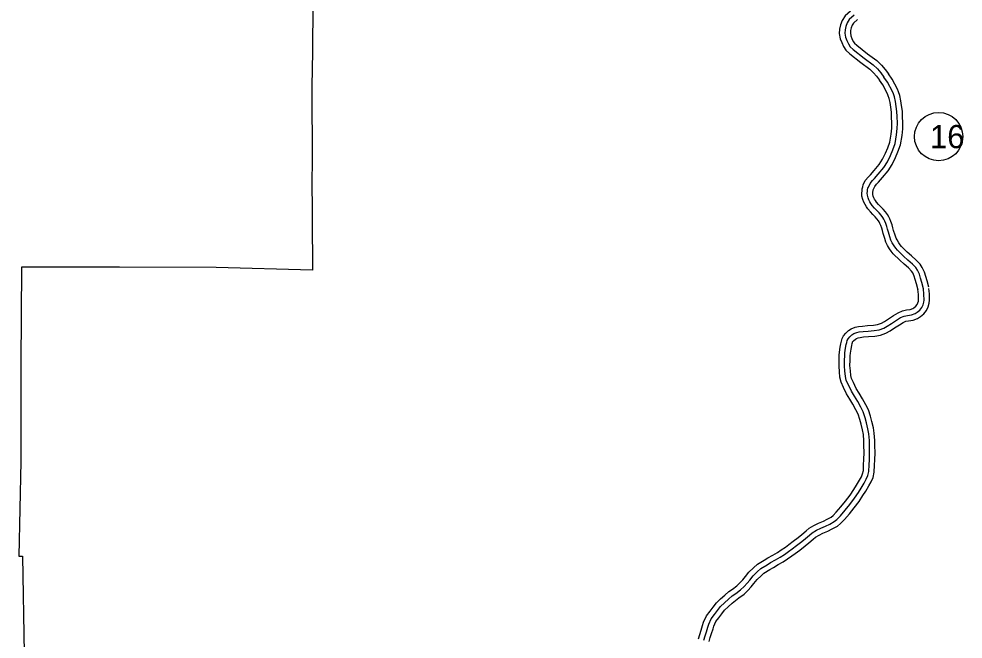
# Model space of a CAD drawing. Extents: x -83719 to 153526, y -11835 to 11446.
# Drawn here: x -2435 to -1575, y 2786 to 3351 of the extents above; entities that cross this region are included whole.
import ezdxf

# ---------------------------------------------------------------- set-up
doc = ezdxf.new("R2010")
doc.units = 0
for name, color, linetype in [('Level 10', 7, 'Continuous'), ('Level 2', 7, 'Continuous'), ('Level 27', 7, 'Continuous'), ('Level 59', 7, 'Continuous')]:
    doc.layers.add(name, color=color, linetype=linetype)

msp = doc.modelspace()

# ---------------------------------------------------------------- linework, layer by layer
at = {"layer": 'Level 10'}
for points in [[(-1677.93, 3358.27), (-1682.78, 3353.99), (-1685.38, 3349.91), (-1686.84, 3345.86), (-1687.68, 3342.04), (-1688.03, 3337.83), (-1687.11, 3333.21), (-1685.81, 3329.63), (-1684.16, 3326.02), (-1682, 3322.61), (-1678.52, 3319.56), (-1668.41, 3311.43), (-1660.31, 3305.5), (-1656.75, 3302.17), (-1654.01, 3299.1), (-1651.52, 3295.47)], [(-1671.31, 3350.79), (-1675.1, 3347.43), (-1676.35, 3345.46), (-1677.21, 3343.08), (-1677.77, 3340.55), (-1677.95, 3338.4), (-1677.45, 3335.9), (-1676.56, 3333.43), (-1675.35, 3330.8), (-1674.32, 3329.18), (-1672.09, 3327.22), (-1662.32, 3319.37), (-1653.91, 3313.21), (-1649.59, 3309.16), (-1646.13, 3305.28), (-1643.27, 3301.12)], [(-1606.59, 3106.74), (-1608.16, 3112.5), (-1609.2, 3116.53), (-1610.49, 3120.56), (-1612.51, 3124.87), (-1614.54, 3127.82), (-1617.95, 3131.53), (-1622.22, 3135.32), (-1626.24, 3138.86), (-1631.43, 3143.93), (-1632.51, 3145.31), (-1633.83, 3147.36), (-1635.48, 3149.85), (-1636.32, 3151.52), (-1637.15, 3154.24), (-1638.56, 3158.46), (-1639.16, 3160.87), (-1639.89, 3163.63), (-1641.05, 3166.8), (-1641.99, 3168.99), (-1642.97, 3171.07), (-1644.21, 3173.1), (-1646.1, 3175.53), (-1648.12, 3177.81), (-1650.18, 3180), (-1652.23, 3182.23), (-1654.07, 3184.35), (-1655.11, 3185.78), (-1655.9, 3187.01), (-1656.54, 3188.29), (-1657.06, 3189.63), (-1657.48, 3191.35), (-1657.54, 3192.32), (-1657.41, 3193.53), (-1657.27, 3194.88), (-1657.12, 3195.47), (-1656.86, 3196.2), (-1655.76, 3198.62), (-1654.09, 3200.7), (-1652.33, 3202.47), (-1648.7, 3206.71), (-1643.58, 3212.79), (-1639.81, 3218.73), (-1636.92, 3224.89), (-1634.65, 3230.1), (-1632.45, 3236.49), (-1630.84, 3244.92), (-1630.28, 3251.22), (-1630.17, 3256.44), (-1630.39, 3262.45), (-1630.63, 3267.26), (-1631.35, 3272.29), (-1632, 3276.74), (-1632.97, 3281.4), (-1634.07, 3284.86), (-1635.18, 3287.37), (-1639.97, 3296.3), (-1643.28, 3301.12)], [(-1616.24, 3104.12), (-1617.82, 3109.93), (-1618.81, 3113.75), (-1619.82, 3116.9), (-1621.21, 3119.88), (-1622.37, 3121.57), (-1624.97, 3124.38), (-1628.84, 3127.83), (-1633.04, 3131.52), (-1638.9, 3137.25), (-1640.67, 3139.51), (-1642.2, 3141.89), (-1644.15, 3144.83), (-1645.63, 3147.79), (-1646.67, 3151.19), (-1648.17, 3155.68), (-1648.84, 3158.39), (-1649.44, 3160.62), (-1650.35, 3163.1), (-1651.12, 3164.89), (-1651.79, 3166.33), (-1652.45, 3167.4), (-1653.81, 3169.14), (-1655.51, 3171.08), (-1657.49, 3173.18), (-1659.69, 3175.57), (-1661.91, 3178.12), (-1663.37, 3180.13), (-1664.62, 3182.08), (-1665.7, 3184.25), (-1666.62, 3186.63), (-1667.4, 3189.83), (-1667.58, 3192.53), (-1667.35, 3194.6), (-1667.14, 3196.59), (-1666.72, 3198.34), (-1666.14, 3199.96), (-1664.33, 3203.92), (-1661.55, 3207.37), (-1659.69, 3209.25), (-1656.32, 3213.18), (-1651.66, 3218.72), (-1648.59, 3223.55), (-1646.04, 3229.01), (-1643.98, 3233.73), (-1642.14, 3239.07), (-1640.76, 3246.3), (-1640.27, 3251.77), (-1640.18, 3256.36), (-1640.38, 3262.02), (-1640.59, 3266.29), (-1641.25, 3270.85), (-1641.85, 3275), (-1642.66, 3278.86), (-1643.43, 3281.31), (-1644.17, 3282.98), (-1648.52, 3291.09), (-1651.52, 3295.46)], [(-1816.08, 2786.5), (-1815.06, 2790.59), (-1813.77, 2794.51), (-1812.5, 2798.64), (-1811.54, 2801.64), (-1808.98, 2807.39), (-1805.62, 2811.68), (-1802.96, 2815.37), (-1799.75, 2819.23), (-1796.06, 2822.92), (-1792.22, 2826.42), (-1788.68, 2829.52), (-1785.19, 2831.85), (-1781.19, 2834.94), (-1778.28, 2837.72), (-1775.73, 2840.4), (-1773.45, 2843.2), (-1770.21, 2847.14), (-1766.17, 2851.2), (-1762.57, 2854.55), (-1756.4, 2858.17), (-1753.21, 2860.19), (-1748.65, 2862.81), (-1744.37, 2865.24), (-1740.8, 2867.57), (-1737.1, 2870.13), (-1733.97, 2872.45), (-1729.87, 2875.41), (-1725.35, 2878.94), (-1722.05, 2881.65), (-1718.32, 2884.85), (-1715.52, 2887.2), (-1711.23, 2889.87), (-1706.99, 2891.85), (-1702.53, 2893.76), (-1699.01, 2895.47), (-1695.37, 2897.48), (-1693.65, 2898.9), (-1690.76, 2901.9), (-1686.52, 2906.82), (-1682.42, 2911.97), (-1678.24, 2917.44), (-1674.85, 2922.65), (-1672.41, 2926.38), (-1669.74, 2930.98), (-1667.94, 2934.05), (-1666.88, 2936.72), (-1666.11, 2939.76), (-1665.94, 2945.16), (-1665.67, 2949.93), (-1665.49, 2956.15), (-1665.6, 2962.59), (-1665.66, 2966.81), (-1666.11, 2972.57), (-1666.81, 2976.88), (-1668.02, 2982.21), (-1669.18, 2986.46), (-1670.8, 2991.29), (-1672.83, 2995.12), (-1675.64, 3000.37), (-1678.33, 3004.99), (-1681.37, 3009.68), (-1684.13, 3015.58), (-1686.46, 3020.3), (-1687.48, 3025.01), (-1687.83, 3029.83), (-1688.28, 3035.01), (-1688.27, 3040.31), (-1687.99, 3044.92), (-1687.88, 3047.67), (-1687.18, 3052.09), (-1686.59, 3055.38), (-1686.16, 3057.78), (-1685.42, 3060.21), (-1684.29, 3062.56), (-1682.17, 3065.02), (-1679.72, 3067.3), (-1677.23, 3069.06), (-1673.59, 3070.42), (-1670.63, 3071.05), (-1666.82, 3071.46), (-1662.24, 3071.83), (-1656.86, 3072.29), (-1653.13, 3072.84), (-1649.64, 3074.17), (-1646.85, 3075.63), (-1643.19, 3078.04), (-1638.68, 3081.05), (-1634.48, 3083.59), (-1630.41, 3085.31), (-1626.84, 3086.13), (-1623.39, 3086.6), (-1621.22, 3087.42), (-1620.05, 3088.12), (-1618.5, 3089.48), (-1617.21, 3091.1), (-1616.41, 3092.74), (-1615.94, 3094.21), (-1615.83, 3095.31), (-1616.05, 3100.23), (-1616.4, 3105.06)], [(-1806.38, 2784.07), (-1805.44, 2787.81), (-1804.24, 2791.47), (-1802.95, 2795.65), (-1802.18, 2798.08), (-1800.35, 2802.19), (-1797.62, 2805.67), (-1795.05, 2809.25), (-1792.36, 2812.48), (-1789.15, 2815.69), (-1785.56, 2818.96), (-1782.59, 2821.56), (-1779.35, 2823.72), (-1774.66, 2827.35), (-1771.19, 2830.66), (-1768.22, 2833.8), (-1765.71, 2836.87), (-1762.79, 2840.42), (-1759.22, 2844.01), (-1756.57, 2846.48), (-1751.19, 2849.63), (-1748.04, 2851.63), (-1743.68, 2854.13), (-1739.17, 2856.69), (-1735.22, 2859.27), (-1731.27, 2862.01), (-1728.07, 2864.38), (-1723.86, 2867.41), (-1719.1, 2871.14), (-1715.62, 2873.99), (-1711.84, 2877.23), (-1709.64, 2879.09), (-1706.46, 2881.06), (-1702.9, 2882.72), (-1698.37, 2884.66), (-1694.41, 2886.59), (-1689.73, 2889.17), (-1686.84, 2891.55), (-1683.36, 2895.17), (-1678.81, 2900.44), (-1674.53, 2905.82), (-1670.07, 2911.67), (-1666.48, 2917.18), (-1663.9, 2921.12), (-1661.1, 2925.94), (-1658.93, 2929.66), (-1657.34, 2933.63), (-1656.15, 2938.36), (-1655.94, 2944.72), (-1655.67, 2949.5), (-1655.49, 2956.1), (-1655.61, 2962.74), (-1655.66, 2967.26), (-1656.17, 2973.77), (-1656.99, 2978.79), (-1658.32, 2984.64), (-1659.61, 2989.37), (-1661.58, 2995.24), (-1664, 2999.82), (-1666.91, 3005.25), (-1669.81, 3010.23), (-1672.6, 3014.54), (-1675.12, 3019.92), (-1676.95, 3023.62), (-1677.56, 3026.43), (-1677.86, 3030.62), (-1678.28, 3035.44), (-1678.27, 3040.01), (-1678.01, 3044.42), (-1677.92, 3046.68), (-1677.32, 3050.42), (-1676.74, 3053.62), (-1676.42, 3055.44), (-1676.08, 3056.56), (-1675.85, 3057.03), (-1674.95, 3058.08), (-1673.4, 3059.52), (-1672.51, 3060.15), (-1670.79, 3060.79), (-1669.05, 3061.16), (-1665.88, 3061.51), (-1661.41, 3061.86), (-1655.69, 3062.35), (-1650.59, 3063.11), (-1645.53, 3065.04), (-1641.78, 3067), (-1637.66, 3069.7), (-1633.32, 3072.61), (-1629.93, 3074.65), (-1627.32, 3075.76), (-1625.04, 3076.28), (-1620.92, 3076.85), (-1616.86, 3078.38), (-1614.14, 3080), (-1611.22, 3082.57), (-1608.71, 3085.74), (-1607.11, 3089.01), (-1606.11, 3092.15), (-1605.81, 3095), (-1606.06, 3100.82), (-1606.43, 3105.8)]]:
    msp.add_lwpolyline(points, dxfattribs=at)
at = {"layer": 'Level 2'}
for points in [[(-2166.12, 3781.27), (-2166.03, 3744.62), (-2165.97, 3740.95), (-2164.82, 3655.33), (-2164.81, 3652.33), (-2164.19, 3566.7), (-2164.17, 3564.33), (-2163.12, 3478.98), (-2163.28, 3475.88), (-2166.92, 3387.5), (-2167.82, 3298.83), (-2167.96, 3296.59)], [(-2167.96, 3296.59), (-2167.95, 3213.09), (-2168.12, 3211.25), (-2167.46, 3124.08), (-2167.54, 3122.34), (-2255.07, 3124.73), (-2343.15, 3125.11), (-2432.22, 3124.97), (-2433.11, 3037.14), (-2432.86, 2948.09), (-2434.74, 2861.95), (-2431.38, 2861.79), (-2430.03, 2773.16), (-2429.67, 2685.78), (-2429.9, 2646.06)]]:
    msp.add_lwpolyline(points, dxfattribs=at)
at = {"layer": 'Level 27'}
msp.add_circle((-1597.62, 3244.03), 22, dxfattribs=at)
at = {"layer": 'Level 59'}
for points in [[(-1674.62, 3354.53), (-1678.94, 3350.71), (-1680.87, 3347.69), (-1682.03, 3344.47), (-1682.73, 3341.29), (-1682.99, 3338.12), (-1682.28, 3334.56), (-1681.18, 3331.53), (-1679.75, 3328.41), (-1678.16, 3325.9), (-1675.3, 3323.39), (-1665.36, 3315.4), (-1657.11, 3309.35), (-1653.17, 3305.66), (-1650.07, 3302.19), (-1647.4, 3298.29)], [(-1611.42, 3105.43), (-1612.99, 3111.21), (-1614.01, 3115.14), (-1615.15, 3118.73), (-1616.86, 3122.38), (-1618.46, 3124.69), (-1621.46, 3127.96), (-1625.53, 3131.57), (-1629.64, 3135.19), (-1635.17, 3140.59), (-1636.59, 3142.41), (-1638.01, 3144.62), (-1639.81, 3147.34), (-1640.97, 3149.66), (-1641.91, 3152.72), (-1643.37, 3157.07), (-1644, 3159.63), (-1644.66, 3162.12), (-1645.7, 3164.95), (-1646.56, 3166.94), (-1647.38, 3168.7), (-1648.33, 3170.25), (-1649.95, 3172.33), (-1651.81, 3174.44), (-1653.84, 3176.59), (-1655.96, 3178.9), (-1657.99, 3181.24), (-1659.24, 3182.96), (-1660.26, 3184.55), (-1661.12, 3186.27), (-1661.84, 3188.13), (-1662.44, 3190.59), (-1662.56, 3192.42), (-1662.38, 3194.06), (-1662.2, 3195.73), (-1661.92, 3196.91), (-1661.5, 3198.08), (-1660.05, 3201.27), (-1657.82, 3204.04), (-1656.01, 3205.86), (-1652.51, 3209.95), (-1647.62, 3215.75), (-1644.2, 3221.14), (-1641.48, 3226.95), (-1639.32, 3231.92), (-1637.3, 3237.78), (-1635.8, 3245.61), (-1635.28, 3251.49), (-1635.17, 3256.4), (-1635.38, 3262.24), (-1635.61, 3266.77), (-1636.3, 3271.57), (-1636.92, 3275.87), (-1637.81, 3280.13), (-1638.75, 3283.09), (-1639.67, 3285.18), (-1644.24, 3293.69), (-1647.4, 3298.29)], [(-1811.23, 2785.28), (-1810.25, 2789.2), (-1809, 2792.99), (-1807.73, 2797.14), (-1806.86, 2799.86), (-1804.66, 2804.79), (-1801.62, 2808.67), (-1799, 2812.31), (-1796.06, 2815.86), (-1792.61, 2819.31), (-1788.89, 2822.69), (-1785.63, 2825.54), (-1782.27, 2827.79), (-1777.92, 2831.15), (-1774.73, 2834.19), (-1771.97, 2837.1), (-1769.58, 2840.04), (-1766.5, 2843.78), (-1762.69, 2847.6), (-1759.57, 2850.52), (-1753.79, 2853.9), (-1750.62, 2855.91), (-1746.16, 2858.47), (-1741.77, 2860.96), (-1738.01, 2863.42), (-1734.18, 2866.07), (-1731.02, 2868.42), (-1726.87, 2871.41), (-1722.22, 2875.04), (-1718.83, 2877.82), (-1715.08, 2881.04), (-1712.58, 2883.14), (-1708.85, 2885.46), (-1704.95, 2887.28), (-1700.45, 2889.21), (-1696.71, 2891.03), (-1692.55, 2893.32), (-1690.24, 2895.22), (-1687.06, 2898.54), (-1682.66, 2903.63), (-1678.47, 2908.89), (-1674.15, 2914.56), (-1670.66, 2919.91), (-1668.15, 2923.75), (-1665.42, 2928.46), (-1663.43, 2931.86), (-1662.11, 2935.18), (-1661.13, 2939.06), (-1660.94, 2944.94), (-1660.67, 2949.71), (-1660.49, 2956.13), (-1660.61, 2962.67), (-1660.66, 2967.04), (-1661.14, 2973.17), (-1661.9, 2977.83), (-1663.17, 2983.42), (-1664.39, 2987.91), (-1666.19, 2993.26), (-1668.41, 2997.47), (-1671.28, 3002.81), (-1674.07, 3007.61), (-1676.99, 3012.11), (-1679.62, 3017.75), (-1681.71, 3021.96), (-1682.52, 3025.72), (-1682.85, 3030.22), (-1683.28, 3035.22), (-1683.27, 3040.16), (-1683, 3044.67), (-1682.9, 3047.17), (-1682.25, 3051.26), (-1681.66, 3054.5), (-1681.29, 3056.61), (-1680.75, 3058.38), (-1680.07, 3059.79), (-1678.56, 3061.55), (-1676.56, 3063.41), (-1674.87, 3064.6), (-1672.19, 3065.61), (-1669.84, 3066.1), (-1666.35, 3066.48), (-1661.83, 3066.85), (-1656.28, 3067.32), (-1651.86, 3067.98), (-1647.59, 3069.6), (-1644.32, 3071.32), (-1640.42, 3073.87), (-1636, 3076.83), (-1632.2, 3079.12), (-1628.86, 3080.53), (-1625.94, 3081.2), (-1622.16, 3081.72), (-1619.04, 3082.9), (-1617.1, 3084.06), (-1614.86, 3086.02), (-1612.96, 3088.42), (-1611.76, 3090.87), (-1611.02, 3093.18), (-1610.82, 3095.16), (-1611.05, 3100.53), (-1611.42, 3105.43)]]:
    msp.add_lwpolyline(points, dxfattribs=at)

# ---------------------------------------------------------------- texts
at = {"layer": 'Level 27'}
msp.add_text('16', height=21.12, dxfattribs=at).set_placement((-1605.49, 3233.47))

doc.saveas('drawing.dxf')
